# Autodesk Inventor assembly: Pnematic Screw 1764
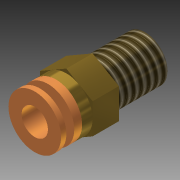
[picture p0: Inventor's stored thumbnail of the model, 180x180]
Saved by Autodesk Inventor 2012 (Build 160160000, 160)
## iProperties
Created: 2010-02
Part Number: Pnematic Screw 1764
Document SubType Name: Assembly
Designer: clee1
Author: clee1
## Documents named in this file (3)
- R:\CAD Archives\Pneumatics_1764\Pneumatics_T_Intersection_1764\Pnewmatic_Screw_1764\Pneumatic_Screw_1764.iam
- R:\CAD Archives\Pneumatics_1764\Pneumatics_T_Intersection_1764\Pnewmatic_Screw_1764\Pneumatic_Screw_Part_1_1764.ipt
- R:\CAD Archives\Pneumatics_1764\Pneumatics_T_Intersection_1764\Pnewmatic_Screw_1764\Pneumatic_Screw_Part_2_1764.ipt
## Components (2 placed, 2 different names)
1. Pneumatic_Screw_Part_1_1764:1 — Insert:1
2. Pneumatic_Screw_Part_2_1764:1 — Insert:1
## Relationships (1: Insert 1)
- Insert:1: Pneumatic_Screw_Part_1_1764:1 ↔ Pneumatic_Screw_Part_2_1764:1
